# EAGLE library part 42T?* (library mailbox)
Xicon Micro-Mini EI-12 Audio Transformers 42TL/42TC/42TM Series Source: http://www.mouser.com//catalog/specsheets/164201.pdf http://www.mouser.com/catalog/specsheets/114225.pdf http://www.mouser.com/catalog/specsheets/164267.pdf
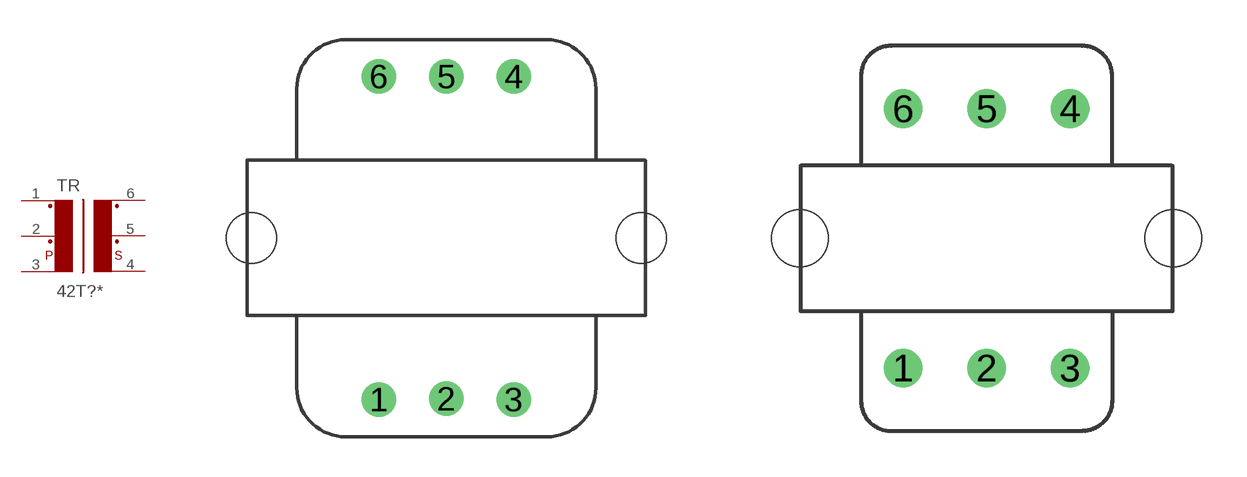
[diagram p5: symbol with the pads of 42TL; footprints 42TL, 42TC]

Designator prefix TR

## 42TL001, 42TL002, 42TL003, 42TL004, 42TL006, 42TL008, 42TL009, 42TL011, 42TL012, 42TL013, 42TL016, 42TL017, 42TL018, 42TL019, 42TL020, 42TL021, 42TL022, 42TL023, 42TL024, 42TL025, 42TL026, 42TL027, 42TL030, 42TL031, 42TL218  [42TL]
1  1  pas
2  2  pas
3  3  pas
4  4  pas
5  5  pas
6  6  pas

## 42TC001, 42TC013, 42TC016  [42TC]
Pads as for 42TL

## 42TC019, 42TC021, 42TC030  [42TC]
1  4  pas
2  5  pas
3  6  pas
4  1  pas
5  2  pas
6  3  pas

## 42TM001, 42TM002, 42TM003, 42TM004, 42TM006, 42TM008, 42TM009, 42TM010, 42TM011, 42TM012, 42TM013, 42TM016, 42TM017, 42TM018, 42TM019, 42TM020, 42TM021, 42TM022, 42TM023, 42TM024, 42TM025, 42TM026, 42TM027, 42TM030, 42TM031, 42TM114, 42TM117, 42TM118  [42TM]
Pads as for 42TL

## Footprint 42TL (pad centres in mm)
Xicon Ultra-Mini Audio Transformer 42TL Series Category: Audio & Signal Transformers Source: http://www.mouser.com//catalog/specsheets/164201.pdf
drill 0.7 pad 1.3 round: 1 -2.54,-6.096; 2 0,-6.068; 3 2.54,-6.096; 4 2.54,6.096; 5 0,6.096; 6 -2.54,6.096
hole 1.9 at -7.353,0
hole 1.9 at 7.353,0

## Footprint 42TC (pad centres in mm)
Xicon Ultra-Mini Audio Transformer 42TC Series Source: http://www.mouser.com/catalog/specsheets/114225.pdf
drill 0.7 pad 1.3 round: 1 -2.794,-4.343; 2 0,-4.343; 3 2.794,-4.343; 4 2.794,4.343; 5 0,4.343; 6 -2.794,4.343
hole 1.9 at -6.248,0
hole 1.9 at 6.248,0

## Footprint 42TM (pad centres in mm)
Xicon Ultra-Mini Audio Transformer 42TM Series Source: http://www.mouser.com/catalog/specsheets/164267.pdf
drill 0.7 pad 1.3 round: 1 -3.556,-6.35; 2 0,-6.35; 3 3.556,-6.35; 4 3.556,6.35; 5 0,6.35; 6 -3.556,6.35
hole 1.9 at -9.982,0
hole 1.9 at 9.982,0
